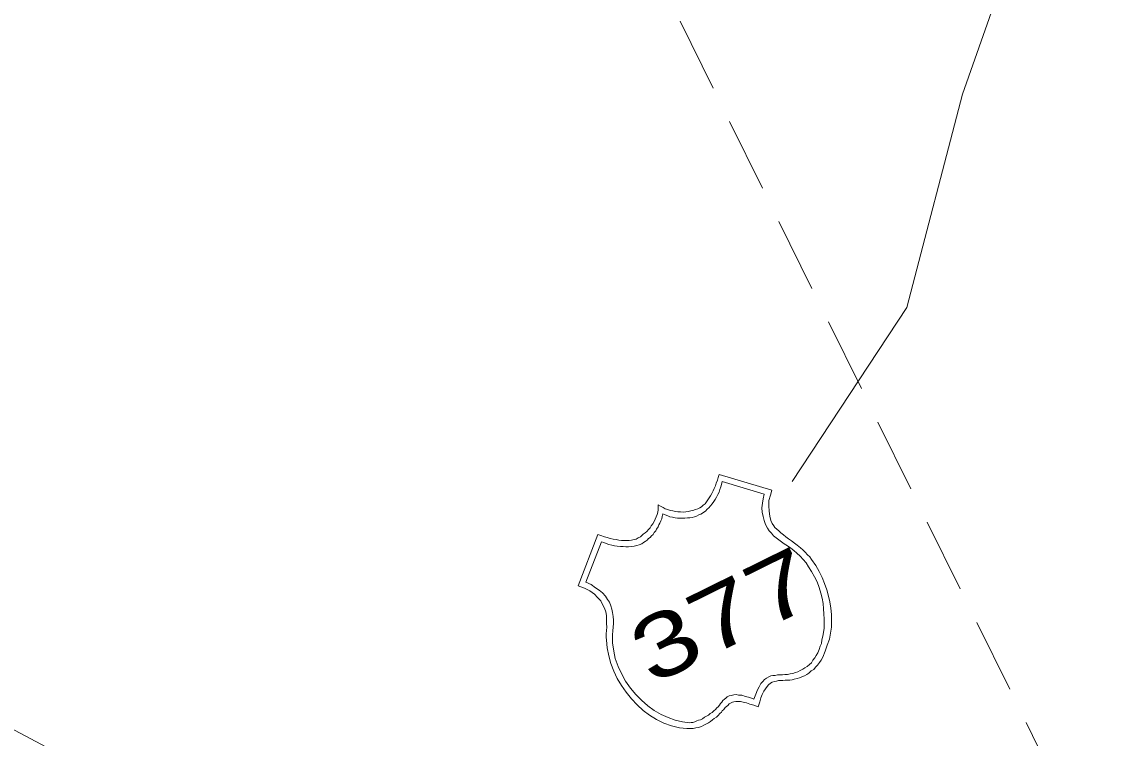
# Model space of a CAD drawing. Extents: x 2356606 to 2371222, y 6973096 to 6982644.
# Drawn here: x 2370773.7 to 2370861.3, y 6980231.5 to 6980289.2 of the extents above; entities that cross this region are included whole.
import ezdxf

# ---------------------------------------------------------------- set-up
doc = ezdxf.new("R2010")
doc.units = 0
doc.header["$LTSCALE"] = 2
doc.linetypes.add('MEDIUM_DASHED', pattern=[4.5, 3, -1.5])
doc.layers.add('62', color=7, linetype='Continuous', lineweight=13)
doc.layers.add('63', color=7, linetype='Continuous', lineweight=13)

msp = doc.modelspace()

# ---------------------------------------------------------------- linework, layer by layer
at = {"layer": '62', "linetype": 'MEDIUM_DASHED'}
msp.add_line((2370774.944, 6980394.196), (2370857.153, 6980227.678), dxfattribs=at)
at = {"layer": '62'}
msp.add_line((2370845.004, 6980266.221), (2370835.784, 6980252.212), dxfattribs=at)
for points in [[(2370861.286, 6980320.676), (2370857.617, 6980309.659), (2370855.496, 6980300.434), (2370849.491, 6980283.413), (2370845.004, 6980266.221)], [(2370818.521, 6980243.817), (2370820.122, 6980247.944), (2370820.363, 6980247.861), (2370820.644, 6980247.749), (2370820.875, 6980247.688), (2370821.106, 6980247.625), (2370821.337, 6980247.564), (2370821.58, 6980247.533), (2370821.801, 6980247.493), (2370822.023, 6980247.45), (2370822.224, 6980247.449), (2370822.424, 6980247.45), (2370822.643, 6980247.457), (2370822.827, 6980247.498), (2370823.028, 6980247.547), (2370823.189, 6980247.577), (2370823.371, 6980247.665), (2370823.552, 6980247.755), (2370823.654, 6980247.856), (2370823.775, 6980247.966), (2370823.927, 6980248.066), (2370824.068, 6980248.185), (2370824.19, 6980248.346), (2370824.321, 6980248.486), (2370824.422, 6980248.634), (2370824.544, 6980248.795), (2370824.646, 6980248.998), (2370824.738, 6980249.169), (2370824.809, 6980249.379), (2370824.9, 6980249.55), (2370824.953, 6980249.75), (2370824.982, 6980249.941), (2370824.983, 6980250.141), (2370824.986, 6980250.344), (2370825.166, 6980250.231), (2370825.366, 6980250.13), (2370825.546, 6980250.018), (2370825.749, 6980249.967), (2370825.94, 6980249.885), (2370826.16, 6980249.845), (2370826.382, 6980249.802), (2370826.571, 6980249.771), (2370826.773, 6980249.772), (2370826.987, 6980249.751), (2370827.197, 6980249.781), (2370827.388, 6980249.797), (2370827.612, 6980249.859), (2370827.772, 6980249.886), (2370827.992, 6980249.947), (2370828.184, 6980250.014), (2370828.325, 6980250.085), (2370828.475, 6980250.185), (2370828.597, 6980250.293), (2370828.762, 6980250.426), (2370828.862, 6980250.575), (2370828.983, 6980250.736), (2370829.085, 6980250.887), (2370829.196, 6980251.068), (2370829.286, 6980251.238), (2370829.41, 6980251.449), (2370829.492, 6980251.64), (2370829.582, 6980251.859), (2370829.655, 6980252.072), (2370829.755, 6980252.322), (2370829.808, 6980252.522), (2370829.89, 6980252.763), (2370834.14, 6980251.526), (2370834.016, 6980251.112), (2370833.903, 6980250.682), (2370833.89, 6980250.248), (2370833.92, 6980249.834), (2370833.967, 6980249.431), (2370834.066, 6980249.078), (2370834.166, 6980248.826), (2370834.286, 6980248.636), (2370834.376, 6980248.504), (2370834.547, 6980248.361), (2370834.684, 6980248.231), (2370834.866, 6980248.067), (2370835.069, 6980247.913), (2370835.27, 6980247.764), (2370835.479, 6980247.592), (2370835.709, 6980247.429), (2370835.95, 6980247.244), (2370836.181, 6980247.084), (2370836.431, 6980246.88), (2370836.64, 6980246.709), (2370836.83, 6980246.527), (2370837.011, 6980246.315), (2370837.202, 6980246.131), (2370837.331, 6980245.919), (2370837.672, 6980245.437), (2370837.951, 6980244.971), (2370838.189, 6980244.488), (2370838.387, 6980243.983), (2370838.577, 6980243.498), (2370838.703, 6980242.985), (2370838.811, 6980242.513), (2370838.889, 6980241.998), (2370838.94, 6980241.494), (2370838.946, 6980240.97)], [(2370838.245, 6980239.746), (2370838.296, 6980240.05), (2370838.348, 6980240.401), (2370838.36, 6980240.784), (2370838.363, 6980241.134), (2370838.335, 6980241.549), (2370838.308, 6980241.96), (2370838.279, 6980242.372), (2370838.191, 6980242.808), (2370838.083, 6980243.23), (2370837.942, 6980243.663), (2370837.794, 6980244.118), (2370837.583, 6980244.54), (2370837.327, 6980244.965), (2370837.095, 6980245.327), (2370836.888, 6980245.651), (2370836.648, 6980245.934), (2370836.418, 6980246.196), (2370836.149, 6980246.439), (2370835.897, 6980246.643), (2370835.665, 6980246.855), (2370835.405, 6980247.028), (2370835.124, 6980247.191), (2370834.923, 6980247.34), (2370834.694, 6980247.503), (2370834.483, 6980247.676), (2370834.271, 6980247.848), (2370834.102, 6980248.043), (2370833.931, 6980248.234), (2370833.771, 6980248.456), (2370833.631, 6980248.738), (2370833.522, 6980249.063), (2370833.434, 6980249.395), (2370833.365, 6980249.738), (2370833.339, 6980250.1), (2370833.378, 6980250.471), (2370833.431, 6980250.824), (2370833.525, 6980251.195), (2370830.138, 6980252.209), (2370830.076, 6980251.978), (2370830.024, 6980251.776), (2370829.954, 6980251.567), (2370829.882, 6980251.355), (2370829.782, 6980251.155), (2370829.679, 6980250.953), (2370829.568, 6980250.775), (2370829.455, 6980250.594), (2370829.313, 6980250.424), (2370829.202, 6980250.243), (2370829.05, 6980250.09), (2370828.93, 6980249.981), (2370828.778, 6980249.832), (2370828.647, 6980249.741), (2370828.534, 6980249.662), (2370828.402, 6980249.572), (2370828.253, 6980249.521), (2370828.07, 6980249.431), (2370827.898, 6980249.373), (2370827.727, 6980249.314), (2370827.516, 6980249.284), (2370827.344, 6980249.276), (2370827.133, 6980249.247), (2370826.932, 6980249.248), (2370826.75, 6980249.259), (2370826.527, 6980249.249), (2370826.338, 6980249.281), (2370826.137, 6980249.332), (2370825.925, 6980249.354), (2370825.755, 6980249.445), (2370825.545, 6980249.515), (2370825.343, 6980249.616), (2370825.302, 6980249.396), (2370825.271, 6980249.206), (2370825.18, 6980249.034), (2370825.119, 6980248.853), (2370825.036, 6980248.714), (2370824.966, 6980248.554), (2370824.853, 6980248.372), (2370824.791, 6980248.241), (2370824.661, 6980248.102), (2370824.559, 6980247.951), (2370824.44, 6980247.84), (2370824.327, 6980247.711), (2370824.193, 6980247.62), (2370824.085, 6980247.491), (2370823.935, 6980247.39), (2370823.803, 6980247.3), (2370823.651, 6980247.202), (2370823.448, 6980247.102), (2370823.267, 6980247.062), (2370823.046, 6980247.004), (2370822.835, 6980246.974), (2370822.593, 6980246.955), (2370822.372, 6980246.946), (2370822.16, 6980246.968), (2370821.927, 6980246.979), (2370821.669, 6980247.001), (2370821.456, 6980247.022), (2370821.245, 6980247.092), (2370820.993, 6980247.145), (2370820.783, 6980247.215)], [(2370820.412, 6980247.36), (2370819.157, 6980244.106), (2370819.578, 6980243.913), (2370819.929, 6980243.658), (2370820.23, 6980243.454), (2370820.491, 6980243.233), (2370820.72, 6980242.971), (2370820.9, 6980242.707), (2370821.061, 6980242.484), (2370821.151, 6980242.202), (2370821.239, 6980241.92), (2370821.298, 6980241.648), (2370821.348, 6980241.343), (2370821.366, 6980241.053), (2370821.374, 6980240.78), (2370821.351, 6980240.468), (2370821.323, 6980240.178), (2370821.299, 6980239.865), (2370821.297, 6980239.21), (2370821.393, 6980238.557), (2370821.521, 6980237.941), (2370821.758, 6980237.307), (2370822.037, 6980236.693), (2370822.347, 6980236.115), (2370822.745, 6980235.561), (2370823.164, 6980235.065), (2370823.625, 6980234.591), (2370824.148, 6980234.146), (2370824.657, 6980233.769), (2370825.221, 6980233.444), (2370825.772, 6980233.191), (2370826.354, 6980232.976), (2370826.94, 6980232.864), (2370827.531, 6980232.778), (2370827.643, 6980232.809), (2370827.775, 6980232.799), (2370827.923, 6980232.847), (2370828.087, 6980232.926), (2370828.236, 6980232.975), (2370828.387, 6980233.026), (2370828.551, 6980233.107), (2370828.72, 6980233.216), (2370828.873, 6980233.316), (2370829.033, 6980233.395), (2370829.176, 6980233.516), (2370829.326, 6980233.615), (2370829.468, 6980233.734), (2370829.589, 6980233.846), (2370829.701, 6980233.976), (2370829.812, 6980234.054), (2370829.913, 6980234.206), (2370830.005, 6980234.326), (2370830.096, 6980234.446), (2370830.188, 6980234.565), (2370830.329, 6980234.686), (2370830.419, 6980234.757), (2370830.541, 6980234.867), (2370830.703, 6980234.946), (2370830.862, 6980234.976), (2370831.065, 6980235.025), (2370831.257, 6980235.044), (2370831.448, 6980235.013), (2370831.71, 6980234.993), (2370832.011, 6980234.889), (2370832.35, 6980234.807), (2370832.692, 6980234.675), (2370832.847, 6980235.076), (2370832.979, 6980235.418), (2370833.1, 6980235.679), (2370833.253, 6980235.929), (2370833.414, 6980236.109), (2370833.546, 6980236.249), (2370833.709, 6980236.379), (2370833.889, 6980236.47), (2370834.053, 6980236.55), (2370834.213, 6980236.578), (2370834.404, 6980236.597), (2370834.585, 6980236.637), (2370834.787, 6980236.636), (2370834.989, 6980236.633), (2370835.169, 6980236.674), (2370835.4, 6980236.662), (2370835.603, 6980236.713), (2370835.836, 6980236.75), (2370836.027, 6980236.82), (2370836.216, 6980236.889), (2370836.419, 6980236.99), (2370836.622, 6980237.089), (2370836.795, 6980237.199), (2370836.985, 6980237.32), (2370837.157, 6980237.478), (2370837.319, 6980237.61), (2370837.44, 6980237.821), (2370837.601, 6980238.001), (2370837.705, 6980238.201), (2370837.847, 6980238.421), (2370837.947, 6980238.673), (2370838.04, 6980238.942), (2370838.132, 6980239.166), (2370838.165, 6980239.458), (2370838.245, 6980239.746)], [(2370820.783, 6980247.215), (2370820.592, 6980247.298), (2370820.412, 6980247.36)], [(2370819.474, 6980243.408), (2370819.044, 6980243.624), (2370818.521, 6980243.817)], [(2370838.946, 6980240.97), (2370838.934, 6980240.487), (2370838.85, 6980239.995), (2370838.768, 6980239.504), (2370838.603, 6980239.021), (2370838.44, 6980238.539), (2370838.247, 6980238.067), (2370838.114, 6980237.825), (2370837.982, 6980237.636), (2370837.809, 6980237.425), (2370837.649, 6980237.244), (2370837.507, 6980237.075), (2370837.314, 6980236.956), (2370837.122, 6980236.785), (2370836.951, 6980236.674), (2370836.76, 6980236.556), (2370836.548, 6980236.475), (2370836.356, 6980236.407), (2370836.165, 6980236.337), (2370835.932, 6980236.298), (2370835.781, 6980236.248), (2370835.571, 6980236.218), (2370835.369, 6980236.221), (2370835.197, 6980236.212), (2370835.018, 6980236.172), (2370834.837, 6980236.182), (2370834.667, 6980236.173), (2370834.513, 6980236.124), (2370834.352, 6980236.094), (2370834.17, 6980236.055), (2370834.018, 6980235.956), (2370833.877, 6980235.836), (2370833.745, 6980235.696), (2370833.612, 6980235.504), (2370833.501, 6980235.323), (2370833.36, 6980235.052), (2370833.237, 6980234.792), (2370833.155, 6980234.45), (2370833.021, 6980234.059), (2370832.682, 6980234.19), (2370832.359, 6980234.283), (2370832.079, 6980234.394), (2370831.836, 6980234.426), (2370831.605, 6980234.488), (2370831.405, 6980234.49), (2370831.233, 6980234.481), (2370831.072, 6980234.451), (2370830.961, 6980234.423), (2370830.8, 6980234.343), (2370830.698, 6980234.291), (2370830.588, 6980234.162), (2370830.476, 6980234.081), (2370830.366, 6980234.003), (2370830.266, 6980233.853), (2370830.14, 6980233.741), (2370830.072, 6980233.631), (2370829.93, 6980233.512), (2370829.799, 6980233.37), (2370829.669, 6980233.232), (2370829.497, 6980233.12), (2370829.344, 6980233.022), (2370829.191, 6980232.871), (2370829.022, 6980232.763), (2370828.82, 6980232.661), (2370828.657, 6980232.583), (2370828.455, 6980232.483), (2370828.224, 6980232.391), (2370828.011, 6980232.364), (2370827.791, 6980232.305), (2370827.539, 6980232.305), (2370827.288, 6980232.307), (2370826.684, 6980232.361), (2370826.049, 6980232.527), (2370825.437, 6980232.749), (2370824.846, 6980233.035), (2370824.274, 6980233.379), (2370823.764, 6980233.754), (2370823.282, 6980234.22), (2370822.813, 6980234.714), (2370822.403, 6980235.241), (2370822.032, 6980235.785), (2370821.684, 6980236.342), (2370821.395, 6980236.927), (2370821.156, 6980237.561), (2370820.989, 6980238.157), (2370820.862, 6980238.821), (2370820.812, 6980239.424), (2370820.795, 6980239.665), (2370820.786, 6980239.937), (2370820.807, 6980240.198), (2370820.841, 6980240.49), (2370820.821, 6980240.784), (2370820.822, 6980241.085), (2370820.813, 6980241.409), (2370820.746, 6980241.7), (2370820.644, 6980242.005), (2370820.496, 6980242.306), (2370820.347, 6980242.611), (2370820.096, 6980242.863), (2370819.835, 6980243.137), (2370819.474, 6980243.408)], [(2370754.237, 6980241.723), (2370759.679, 6980239.289), (2370775.687, 6980230.804), (2370787.493, 6980217.661), (2370796.976, 6980207.036), (2370808.115, 6980203.175), (2370827.813, 6980197.635), (2370838.663, 6980195.838), (2370856.034, 6980192.821), (2370873.785, 6980182.887)]]:
    msp.add_lwpolyline(points, dxfattribs=at)
at = {"layer": '63', "linetype": 'MEDIUM_DASHED'}
msp.add_line((2370774.944, 6980394.196), (2370857.153, 6980227.678), dxfattribs=at)
at = {"layer": '63'}
msp.add_line((2370845.004, 6980266.221), (2370835.784, 6980252.212), dxfattribs=at)
for points in [[(2370861.286, 6980320.676), (2370857.617, 6980309.659), (2370855.496, 6980300.434), (2370849.491, 6980283.413), (2370845.004, 6980266.221)], [(2370818.521, 6980243.817), (2370820.122, 6980247.944), (2370820.363, 6980247.861), (2370820.644, 6980247.749), (2370820.875, 6980247.688), (2370821.106, 6980247.625), (2370821.337, 6980247.564), (2370821.58, 6980247.533), (2370821.801, 6980247.493), (2370822.023, 6980247.45), (2370822.224, 6980247.449), (2370822.424, 6980247.45), (2370822.643, 6980247.457), (2370822.827, 6980247.498), (2370823.028, 6980247.547), (2370823.189, 6980247.577), (2370823.371, 6980247.665), (2370823.552, 6980247.755), (2370823.654, 6980247.856), (2370823.775, 6980247.966), (2370823.927, 6980248.066), (2370824.068, 6980248.185), (2370824.19, 6980248.346), (2370824.321, 6980248.486), (2370824.422, 6980248.634), (2370824.544, 6980248.795), (2370824.646, 6980248.998), (2370824.738, 6980249.169), (2370824.809, 6980249.379), (2370824.9, 6980249.55), (2370824.953, 6980249.75), (2370824.982, 6980249.941), (2370824.983, 6980250.141), (2370824.986, 6980250.344), (2370825.166, 6980250.231), (2370825.366, 6980250.13), (2370825.546, 6980250.018), (2370825.749, 6980249.967), (2370825.94, 6980249.885), (2370826.16, 6980249.845), (2370826.382, 6980249.802), (2370826.571, 6980249.771), (2370826.773, 6980249.772), (2370826.987, 6980249.751), (2370827.197, 6980249.781), (2370827.388, 6980249.797), (2370827.612, 6980249.859), (2370827.772, 6980249.886), (2370827.992, 6980249.947), (2370828.184, 6980250.014), (2370828.325, 6980250.085), (2370828.475, 6980250.185), (2370828.597, 6980250.293), (2370828.762, 6980250.426), (2370828.862, 6980250.575), (2370828.983, 6980250.736), (2370829.085, 6980250.887), (2370829.196, 6980251.068), (2370829.286, 6980251.238), (2370829.41, 6980251.449), (2370829.492, 6980251.64), (2370829.582, 6980251.859), (2370829.655, 6980252.072), (2370829.755, 6980252.322), (2370829.808, 6980252.522), (2370829.89, 6980252.763), (2370834.14, 6980251.526), (2370834.016, 6980251.112), (2370833.903, 6980250.682), (2370833.89, 6980250.248), (2370833.92, 6980249.834), (2370833.967, 6980249.431), (2370834.066, 6980249.078), (2370834.166, 6980248.826), (2370834.286, 6980248.636), (2370834.376, 6980248.504), (2370834.547, 6980248.361), (2370834.684, 6980248.231), (2370834.866, 6980248.067), (2370835.069, 6980247.913), (2370835.27, 6980247.764), (2370835.479, 6980247.592), (2370835.709, 6980247.429), (2370835.95, 6980247.244), (2370836.181, 6980247.084), (2370836.431, 6980246.88), (2370836.64, 6980246.709), (2370836.83, 6980246.527), (2370837.011, 6980246.315), (2370837.202, 6980246.131), (2370837.331, 6980245.919), (2370837.672, 6980245.437), (2370837.951, 6980244.971), (2370838.189, 6980244.488), (2370838.387, 6980243.983), (2370838.577, 6980243.498), (2370838.703, 6980242.985), (2370838.811, 6980242.513), (2370838.889, 6980241.998), (2370838.94, 6980241.494), (2370838.946, 6980240.97)], [(2370838.245, 6980239.746), (2370838.296, 6980240.05), (2370838.348, 6980240.401), (2370838.36, 6980240.784), (2370838.363, 6980241.134), (2370838.335, 6980241.549), (2370838.308, 6980241.96), (2370838.279, 6980242.372), (2370838.191, 6980242.808), (2370838.083, 6980243.23), (2370837.942, 6980243.663), (2370837.794, 6980244.118), (2370837.583, 6980244.54), (2370837.327, 6980244.965), (2370837.095, 6980245.327), (2370836.888, 6980245.651), (2370836.648, 6980245.934), (2370836.418, 6980246.196), (2370836.149, 6980246.439), (2370835.897, 6980246.643), (2370835.665, 6980246.855), (2370835.405, 6980247.028), (2370835.124, 6980247.191), (2370834.923, 6980247.34), (2370834.694, 6980247.503), (2370834.483, 6980247.676), (2370834.271, 6980247.848), (2370834.102, 6980248.043), (2370833.931, 6980248.234), (2370833.771, 6980248.456), (2370833.631, 6980248.738), (2370833.522, 6980249.063), (2370833.434, 6980249.395), (2370833.365, 6980249.738), (2370833.339, 6980250.1), (2370833.378, 6980250.471), (2370833.431, 6980250.824), (2370833.525, 6980251.195), (2370830.138, 6980252.209), (2370830.076, 6980251.978), (2370830.024, 6980251.776), (2370829.954, 6980251.567), (2370829.882, 6980251.355), (2370829.782, 6980251.155), (2370829.679, 6980250.953), (2370829.568, 6980250.775), (2370829.455, 6980250.594), (2370829.313, 6980250.424), (2370829.202, 6980250.243), (2370829.05, 6980250.09), (2370828.93, 6980249.981), (2370828.778, 6980249.832), (2370828.647, 6980249.741), (2370828.534, 6980249.662), (2370828.402, 6980249.572), (2370828.253, 6980249.521), (2370828.07, 6980249.431), (2370827.898, 6980249.373), (2370827.727, 6980249.314), (2370827.516, 6980249.284), (2370827.344, 6980249.276), (2370827.133, 6980249.247), (2370826.932, 6980249.248), (2370826.75, 6980249.259), (2370826.527, 6980249.249), (2370826.338, 6980249.281), (2370826.137, 6980249.332), (2370825.925, 6980249.354), (2370825.755, 6980249.445), (2370825.545, 6980249.515), (2370825.343, 6980249.616), (2370825.302, 6980249.396), (2370825.271, 6980249.206), (2370825.18, 6980249.034), (2370825.119, 6980248.853), (2370825.036, 6980248.714), (2370824.966, 6980248.554), (2370824.853, 6980248.372), (2370824.791, 6980248.241), (2370824.661, 6980248.102), (2370824.559, 6980247.951), (2370824.44, 6980247.84), (2370824.327, 6980247.711), (2370824.193, 6980247.62), (2370824.085, 6980247.491), (2370823.935, 6980247.39), (2370823.803, 6980247.3), (2370823.651, 6980247.202), (2370823.448, 6980247.102), (2370823.267, 6980247.062), (2370823.046, 6980247.004), (2370822.835, 6980246.974), (2370822.593, 6980246.955), (2370822.372, 6980246.946), (2370822.16, 6980246.968), (2370821.927, 6980246.979), (2370821.669, 6980247.001), (2370821.456, 6980247.022), (2370821.245, 6980247.092), (2370820.993, 6980247.145), (2370820.783, 6980247.215)], [(2370820.412, 6980247.36), (2370819.157, 6980244.106), (2370819.578, 6980243.913), (2370819.929, 6980243.658), (2370820.23, 6980243.454), (2370820.491, 6980243.233), (2370820.72, 6980242.971), (2370820.9, 6980242.707), (2370821.061, 6980242.484), (2370821.151, 6980242.202), (2370821.239, 6980241.92), (2370821.298, 6980241.648), (2370821.348, 6980241.343), (2370821.366, 6980241.053), (2370821.374, 6980240.78), (2370821.351, 6980240.468), (2370821.323, 6980240.178), (2370821.299, 6980239.865), (2370821.297, 6980239.21), (2370821.393, 6980238.557), (2370821.521, 6980237.941), (2370821.758, 6980237.307), (2370822.037, 6980236.693), (2370822.347, 6980236.115), (2370822.745, 6980235.561), (2370823.164, 6980235.065), (2370823.625, 6980234.591), (2370824.148, 6980234.146), (2370824.657, 6980233.769), (2370825.221, 6980233.444), (2370825.772, 6980233.191), (2370826.354, 6980232.976), (2370826.94, 6980232.864), (2370827.531, 6980232.778), (2370827.643, 6980232.809), (2370827.775, 6980232.799), (2370827.923, 6980232.847), (2370828.087, 6980232.926), (2370828.236, 6980232.975), (2370828.387, 6980233.026), (2370828.551, 6980233.107), (2370828.72, 6980233.216), (2370828.873, 6980233.316), (2370829.033, 6980233.395), (2370829.176, 6980233.516), (2370829.326, 6980233.615), (2370829.468, 6980233.734), (2370829.589, 6980233.846), (2370829.701, 6980233.976), (2370829.812, 6980234.054), (2370829.913, 6980234.206), (2370830.005, 6980234.326), (2370830.096, 6980234.446), (2370830.188, 6980234.565), (2370830.329, 6980234.686), (2370830.419, 6980234.757), (2370830.541, 6980234.867), (2370830.703, 6980234.946), (2370830.862, 6980234.976), (2370831.065, 6980235.025), (2370831.257, 6980235.044), (2370831.448, 6980235.013), (2370831.71, 6980234.993), (2370832.011, 6980234.889), (2370832.35, 6980234.807), (2370832.692, 6980234.675), (2370832.847, 6980235.076), (2370832.979, 6980235.418), (2370833.1, 6980235.679), (2370833.253, 6980235.929), (2370833.414, 6980236.109), (2370833.546, 6980236.249), (2370833.709, 6980236.379), (2370833.889, 6980236.47), (2370834.053, 6980236.55), (2370834.213, 6980236.578), (2370834.404, 6980236.597), (2370834.585, 6980236.637), (2370834.787, 6980236.636), (2370834.989, 6980236.633), (2370835.169, 6980236.674), (2370835.4, 6980236.662), (2370835.603, 6980236.713), (2370835.836, 6980236.75), (2370836.027, 6980236.82), (2370836.216, 6980236.889), (2370836.419, 6980236.99), (2370836.622, 6980237.089), (2370836.795, 6980237.199), (2370836.985, 6980237.32), (2370837.157, 6980237.478), (2370837.319, 6980237.61), (2370837.44, 6980237.821), (2370837.601, 6980238.001), (2370837.705, 6980238.201), (2370837.847, 6980238.421), (2370837.947, 6980238.673), (2370838.04, 6980238.942), (2370838.132, 6980239.166), (2370838.165, 6980239.458), (2370838.245, 6980239.746)], [(2370820.783, 6980247.215), (2370820.592, 6980247.298), (2370820.412, 6980247.36)], [(2370819.474, 6980243.408), (2370819.044, 6980243.624), (2370818.521, 6980243.817)], [(2370838.946, 6980240.97), (2370838.934, 6980240.487), (2370838.85, 6980239.995), (2370838.768, 6980239.504), (2370838.603, 6980239.021), (2370838.44, 6980238.539), (2370838.247, 6980238.067), (2370838.114, 6980237.825), (2370837.982, 6980237.636), (2370837.809, 6980237.425), (2370837.649, 6980237.244), (2370837.507, 6980237.075), (2370837.314, 6980236.956), (2370837.122, 6980236.785), (2370836.951, 6980236.674), (2370836.76, 6980236.556), (2370836.548, 6980236.475), (2370836.356, 6980236.407), (2370836.165, 6980236.337), (2370835.932, 6980236.298), (2370835.781, 6980236.248), (2370835.571, 6980236.218), (2370835.369, 6980236.221), (2370835.197, 6980236.212), (2370835.018, 6980236.172), (2370834.837, 6980236.182), (2370834.667, 6980236.173), (2370834.513, 6980236.124), (2370834.352, 6980236.094), (2370834.17, 6980236.055), (2370834.018, 6980235.956), (2370833.877, 6980235.836), (2370833.745, 6980235.696), (2370833.612, 6980235.504), (2370833.501, 6980235.323), (2370833.36, 6980235.052), (2370833.237, 6980234.792), (2370833.155, 6980234.45), (2370833.021, 6980234.059), (2370832.682, 6980234.19), (2370832.359, 6980234.283), (2370832.079, 6980234.394), (2370831.836, 6980234.426), (2370831.605, 6980234.488), (2370831.405, 6980234.49), (2370831.233, 6980234.481), (2370831.072, 6980234.451), (2370830.961, 6980234.423), (2370830.8, 6980234.343), (2370830.698, 6980234.291), (2370830.588, 6980234.162), (2370830.476, 6980234.081), (2370830.366, 6980234.003), (2370830.266, 6980233.853), (2370830.14, 6980233.741), (2370830.072, 6980233.631), (2370829.93, 6980233.512), (2370829.799, 6980233.37), (2370829.669, 6980233.232), (2370829.497, 6980233.12), (2370829.344, 6980233.022), (2370829.191, 6980232.871), (2370829.022, 6980232.763), (2370828.82, 6980232.661), (2370828.657, 6980232.583), (2370828.455, 6980232.483), (2370828.224, 6980232.391), (2370828.011, 6980232.364), (2370827.791, 6980232.305), (2370827.539, 6980232.305), (2370827.288, 6980232.307), (2370826.684, 6980232.361), (2370826.049, 6980232.527), (2370825.437, 6980232.749), (2370824.846, 6980233.035), (2370824.274, 6980233.379), (2370823.764, 6980233.754), (2370823.282, 6980234.22), (2370822.813, 6980234.714), (2370822.403, 6980235.241), (2370822.032, 6980235.785), (2370821.684, 6980236.342), (2370821.395, 6980236.927), (2370821.156, 6980237.561), (2370820.989, 6980238.157), (2370820.862, 6980238.821), (2370820.812, 6980239.424), (2370820.795, 6980239.665), (2370820.786, 6980239.937), (2370820.807, 6980240.198), (2370820.841, 6980240.49), (2370820.821, 6980240.784), (2370820.822, 6980241.085), (2370820.813, 6980241.409), (2370820.746, 6980241.7), (2370820.644, 6980242.005), (2370820.496, 6980242.306), (2370820.347, 6980242.611), (2370820.096, 6980242.863), (2370819.835, 6980243.137), (2370819.474, 6980243.408)], [(2370754.237, 6980241.723), (2370759.679, 6980239.289), (2370775.687, 6980230.804), (2370787.493, 6980217.661), (2370796.976, 6980207.036), (2370808.115, 6980203.175), (2370827.813, 6980197.635), (2370838.663, 6980195.838), (2370856.034, 6980192.821), (2370873.785, 6980182.887)]]:
    msp.add_lwpolyline(points, dxfattribs=at)

# ---------------------------------------------------------------- texts
at = {"layer": '62', "width": 1.35}
msp.add_text('377', height=5.099, rotation=26.268, dxfattribs=at).set_placement((2370824.428, 6980235.763))
at = {"layer": '63', "width": 1.35}
msp.add_text('377', height=5.099, rotation=26.268, dxfattribs=at).set_placement((2370824.428, 6980235.763))

doc.saveas('drawing.dxf')
